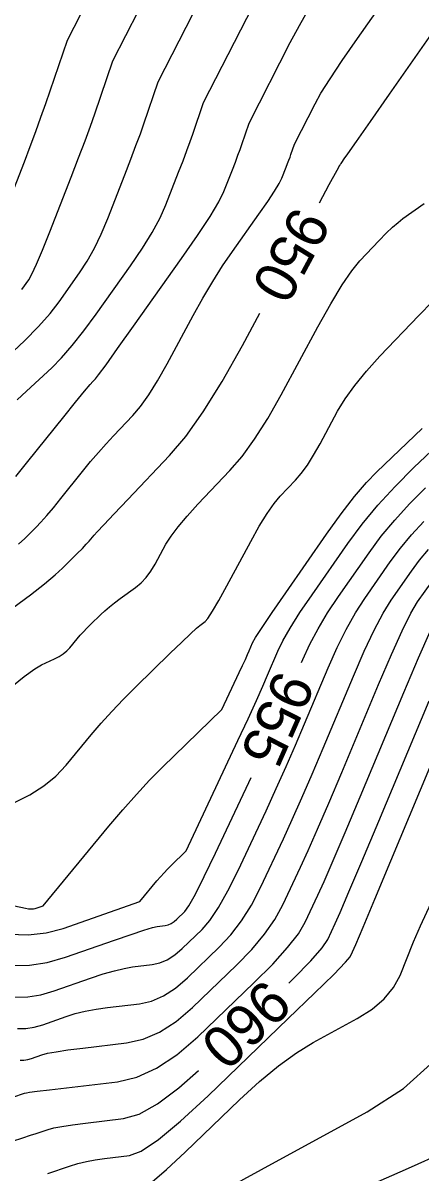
# Model space of a CAD drawing. Extents: x 2175772 to 2185556, y 721391 to 722853.
# Drawn here: x 2178685.3 to 2178711.9, y 721892.9 to 721969.8 of the extents above; entities that cross this region are included whole.
import ezdxf

# ---------------------------------------------------------------- set-up
doc = ezdxf.new("R2010")
doc.units = 0
doc.layers.add('DT_X_Contour_Major', color=7, linetype='Continuous')
doc.layers.add('DT_X_Contour_Minor', color=7, linetype='Continuous')

msp = doc.modelspace()

# ---------------------------------------------------------------- linework, layer by layer
at = {"layer": 'DT_X_Contour_Major'}
for points in [[(2178685.222, 721952.012), (2178685.682, 721952.66), (2178685.9, 721953.044), (2178686.208, 721953.709), (2178686.606, 721954.655), (2178687.095, 721955.883), (2178688.519, 721959.531), (2178689.019, 721960.823), (2178689.449, 721961.962), (2178689.811, 721962.948), (2178690.104, 721963.781), (2178691.309, 721967.314), (2178694.779, 721974.115)], [(2178705.132, 721957.827), (2178705.785, 721959.035), (2178706.309, 721960.006), (2178706.486, 721960.33), (2178706.491, 721960.336), (2178706.493, 721960.338), (2178706.495, 721960.34), (2178706.497, 721960.341), (2178706.498, 721960.342), (2178706.504, 721960.347), (2178706.508, 721960.35), (2178706.516, 721960.361), (2178706.538, 721960.394), (2178706.575, 721960.448), (2178706.626, 721960.523), (2178706.782, 721960.753), (2178707.015, 721961.089), (2178707.6, 721961.925), (2178708.536, 721963.261), (2178709.823, 721965.097), (2178713.722, 721970.66)], [(2178684.621, 721930.711), (2178685.792, 721931.595), (2178686.736, 721932.333), (2178687.451, 721932.925), (2178687.938, 721933.37), (2178688.933, 721934.363), (2178689.269, 721934.701), (2178689.533, 721934.972), (2178689.724, 721935.175), (2178689.842, 721935.31), (2178690.06, 721935.581), (2178690.262, 721935.807), (2178690.704, 721936.283), (2178691.387, 721937.006), (2178692.31, 721937.979), (2178695.092, 721940.905), (2178696.18, 721942.188), (2178697.355, 721943.843), (2178698.618, 721945.87), (2178699.97, 721948.268), (2178701.141, 721950.436)], [(2178703.934, 721927.057), (2178704.022, 721927.265), (2178704.486, 721928.283), (2178705.037, 721929.324), (2178705.674, 721930.389), (2178706.398, 721931.477), (2178708.445, 721934.411), (2178709.257, 721935.507), (2178710.158, 721936.596), (2178711.149, 721937.677), (2178712.23, 721938.75)], [(2178703.08, 721905.601), (2178703.402, 721905.917), (2178704.541, 721907.095), (2178705.3, 721907.964), (2178705.679, 721908.523), (2178706.186, 721909.601), (2178706.51, 721910.332), (2178707.102, 721911.717), (2178707.963, 721913.754), (2178709.092, 721916.445), (2178712.46, 721924.491)], [(2178684.585, 721906.794), (2178685.739, 721906.81), (2178686.925, 721906.993), (2178688.141, 721907.342), (2178691.427, 721908.496), (2178692.529, 721908.877), (2178693.373, 721909.156), (2178693.958, 721909.333), (2178694.284, 721909.408), (2178694.809, 721909.469), (2178695.006, 721909.513), (2178695.203, 721909.599), (2178695.4, 721909.726), (2178695.598, 721909.895), (2178696.123, 721910.4), (2178696.4, 721910.787), (2178696.835, 721911.569), (2178697.428, 721912.746), (2178698.18, 721914.318), (2178700.395, 721919.035), (2178700.551, 721919.369)], [(2178676.882, 721892.488), (2178678.768, 721893.126), (2178680.261, 721893.626), (2178681.363, 721893.989), (2178683.777, 721894.774), (2178684.606, 721895.044), (2178685.283, 721895.265), (2178685.809, 721895.437), (2178686.182, 721895.561), (2178686.975, 721895.826), (2178687.355, 721895.926), (2178687.898, 721896.03), (2178688.604, 721896.137), (2178689.475, 721896.248), (2178692.014, 721896.546), (2178693.06, 721896.849), (2178694.296, 721897.534), (2178695.72, 721898.602), (2178697.027, 721899.777)]]:
    msp.add_lwpolyline(points, dxfattribs=at)
at = {"layer": 'DT_X_Contour_Minor'}
for points in [[(2178684.291, 721947.527), (2178685.401, 721948.586), (2178686.341, 721949.55), (2178687.111, 721950.42), (2178687.712, 721951.195), (2178689.089, 721953.135), (2178689.594, 721953.908), (2178690.077, 721954.773), (2178690.537, 721955.73), (2178690.975, 721956.779), (2178692.114, 721959.697), (2178692.514, 721960.73), (2178692.858, 721961.641), (2178693.148, 721962.43), (2178693.382, 721963.096), (2178694.346, 721965.922), (2178699.503, 721976.031)], [(2178684.993, 721934.981), (2178685.421, 721935.363), (2178686.184, 721936.124), (2178686.502, 721936.458), (2178686.884, 721936.89), (2178687.331, 721937.419), (2178687.841, 721938.046), (2178689.289, 721939.849), (2178689.825, 721940.505), (2178690.348, 721941.119), (2178690.856, 721941.693), (2178691.35, 721942.226), (2178692.649, 721943.592), (2178693.157, 721944.192), (2178693.707, 721944.966), (2178694.298, 721945.915), (2178694.932, 721947.039), (2178696.676, 721950.269), (2178697.331, 721951.445), (2178697.988, 721952.553), (2178698.648, 721953.591), (2178699.31, 721954.56), (2178701.078, 721957.052), (2178701.671, 721957.903), (2178702.125, 721958.59), (2178702.44, 721959.111), (2178702.616, 721959.466), (2178702.9, 721960.193), (2178703, 721960.451), (2178703.085, 721960.678), (2178703.158, 721960.874), (2178703.216, 721961.04), (2178703.456, 721961.744), (2178704.83, 721964.437), (2178705.229, 721965.144), (2178705.837, 721966.11), (2178706.655, 721967.336), (2178707.682, 721968.821), (2178710.7, 721973.126)], [(2178683.492, 721955.696), (2178685.391, 721960.564), (2178685.786, 721961.59), (2178686.157, 721962.582), (2178686.503, 721963.541), (2178686.826, 721964.467), (2178688.273, 721968.706), (2178690.054, 721972.199)], [(2178684.917, 721944.631), (2178685.533, 721945.222), (2178687.218, 721946.783), (2178687.879, 721947.446), (2178688.597, 721948.267), (2178689.371, 721949.244), (2178690.202, 721950.377), (2178692.496, 721953.61), (2178693.288, 721954.773), (2178693.945, 721955.838), (2178694.468, 721956.805), (2178694.856, 721957.674), (2178695.71, 721959.862), (2178696.009, 721960.637), (2178696.267, 721961.32), (2178696.484, 721961.911), (2178696.66, 721962.411), (2178697.383, 721964.529), (2178701.516, 721972.631)], [(2178684.818, 721939.515), (2178685.629, 721940.518), (2178688.024, 721943.5), (2178688.819, 721944.487), (2178689.406, 721945.21), (2178689.787, 721945.67), (2178689.96, 721945.866), (2178690.146, 721946.038), (2178690.357, 721946.307), (2178690.852, 721946.983), (2178691.631, 721948.068), (2178692.693, 721949.56), (2178695.902, 721954.084), (2178696.982, 721955.637), (2178697.814, 721956.902), (2178698.399, 721957.88), (2178698.736, 721958.57), (2178699.305, 721960.028), (2178699.504, 721960.544), (2178699.676, 721960.999), (2178699.821, 721961.393), (2178699.938, 721961.726), (2178700.42, 721963.137), (2178703.173, 721968.534), (2178703.782, 721969.678), (2178704.428, 721970.797)], [(2178684.41, 721925.34), (2178685.376, 721926.118), (2178686.086, 721926.644), (2178686.539, 721926.916), (2178687.408, 721927.306), (2178687.717, 721927.463), (2178687.991, 721927.639), (2178688.23, 721927.835), (2178688.435, 721928.052), (2178688.934, 721928.656), (2178689.13, 721928.885), (2178689.344, 721929.121), (2178689.574, 721929.362), (2178689.822, 721929.609), (2178690.506, 721930.276), (2178690.779, 721930.53), (2178691.084, 721930.791), (2178691.422, 721931.06), (2178691.793, 721931.335), (2178692.825, 721932.081), (2178693.197, 721932.388), (2178693.54, 721932.75), (2178693.855, 721933.168), (2178694.14, 721933.641), (2178694.863, 721934.976), (2178695.2, 721935.519), (2178695.669, 721936.148), (2178696.27, 721936.861), (2178697.003, 721937.659), (2178699.135, 721939.901), (2178699.95, 721940.849), (2178700.794, 721942.012), (2178701.667, 721943.39), (2178702.57, 721944.982), (2178705.018, 721949.514), (2178705.882, 721951.066), (2178706.638, 721952.32), (2178707.287, 721953.278), (2178707.829, 721953.938), (2178709.129, 721955.305), (2178709.594, 721955.78), (2178710.013, 721956.181), (2178710.386, 721956.508), (2178710.712, 721956.761), (2178712.129, 721957.767)], [(2178684.726, 721917.688), (2178685.764, 721918.213), (2178686.686, 721918.807), (2178687.491, 721919.467), (2178688.179, 721920.196), (2178689.86, 721922.228), (2178690.519, 721923), (2178691.236, 721923.792), (2178692.012, 721924.604), (2178692.846, 721925.435), (2178695.146, 721927.678), (2178695.917, 721928.426), (2178696.505, 721928.987), (2178696.909, 721929.361), (2178697.13, 721929.548), (2178697.474, 721929.796), (2178697.662, 721930.017), (2178697.968, 721930.491), (2178698.392, 721931.219), (2178698.933, 721932.201), (2178700.533, 721935.159), (2178701.106, 721936.18), (2178701.625, 721937.024), (2178702.089, 721937.692), (2178702.5, 721938.184), (2178703.523, 721939.259), (2178703.913, 721939.714), (2178704.318, 721940.272), (2178704.737, 721940.933), (2178705.17, 721941.696), (2178706.345, 721943.871), (2178706.852, 721944.712), (2178707.492, 721945.605), (2178708.265, 721946.55), (2178709.172, 721947.547), (2178711.768, 721950.274), (2178712.695, 721951.222)], [(2178684.35, 721908.885), (2178685.637, 721908.845), (2178686.849, 721908.976), (2178687.987, 721909.277), (2178693.123, 721911.081), (2178694.257, 721912.451), (2178694.497, 721912.735), (2178694.731, 721912.999), (2178694.959, 721913.243), (2178695.181, 721913.466), (2178696.204, 721914.464), (2178699.67, 721921.843), (2178700.352, 721923.302), (2178700.911, 721924.517), (2178701.347, 721925.486), (2178701.661, 721926.212), (2178702.334, 721927.82), (2178702.667, 721928.509), (2178703.161, 721929.368), (2178703.816, 721930.398), (2178704.633, 721931.599), (2178707.025, 721935.028), (2178707.974, 721936.31), (2178709.028, 721937.583), (2178710.187, 721938.846), (2178711.45, 721940.1), (2178714.958, 721943.433)], [(2178679.306, 721911.928), (2178685.457, 721910.623), (2178685.663, 721910.588), (2178685.842, 721910.574), (2178685.994, 721910.581), (2178686.12, 721910.61), (2178686.645, 721910.795), (2178691.046, 721916.115), (2178691.977, 721917.217), (2178692.886, 721918.241), (2178693.771, 721919.187), (2178694.634, 721920.056), (2178698.606, 721923.929), (2178699.759, 721926.385), (2178699.986, 721926.871), (2178700.172, 721927.275), (2178700.318, 721927.598), (2178700.422, 721927.84), (2178700.646, 721928.375), (2178700.848, 721928.735), (2178701.286, 721929.412), (2178701.959, 721930.408), (2178702.868, 721931.721), (2178705.605, 721935.646), (2178706.585, 721937.011), (2178707.471, 721938.163), (2178708.263, 721939.102), (2178708.961, 721939.828), (2178712.001, 721942.716)], [(2178684.763, 721904.684), (2178685.614, 721904.695), (2178686.488, 721904.83), (2178687.385, 721905.087), (2178689.807, 721905.938), (2178690.664, 721906.225), (2178691.419, 721906.446), (2178692.071, 721906.602), (2178692.621, 721906.693), (2178693.949, 721906.849), (2178694.448, 721906.96), (2178694.947, 721907.177), (2178695.445, 721907.499), (2178695.945, 721907.926), (2178697.276, 721909.206), (2178697.8, 721909.813), (2178698.376, 721910.674), (2178699.002, 721911.79), (2178699.68, 721913.159), (2178701.554, 721917.148), (2178702.242, 721918.633), (2178702.902, 721920.096), (2178703.534, 721921.537), (2178704.138, 721922.956), (2178705.709, 721926.711), (2178706.305, 721928.057), (2178706.912, 721929.28), (2178707.532, 721930.379), (2178708.164, 721931.355), (2178709.864, 721933.794), (2178710.539, 721934.705), (2178711.289, 721935.61), (2178712.112, 721936.508)], [(2178684.941, 721902.573), (2178685.489, 721902.58), (2178686.051, 721902.667), (2178686.629, 721902.833), (2178688.188, 721903.38), (2178688.799, 721903.572), (2178689.465, 721903.735), (2178690.184, 721903.871), (2178690.957, 721903.979), (2178693.089, 721904.229), (2178693.889, 721904.408), (2178694.69, 721904.755), (2178695.49, 721905.272), (2178696.292, 721905.958), (2178698.428, 721908.012), (2178699.201, 721908.839), (2178699.917, 721909.78), (2178700.577, 721910.833), (2178701.179, 721912), (2178702.712, 721915.261), (2178703.309, 721916.558), (2178703.952, 721918.001), (2178704.641, 721919.591), (2178705.376, 721921.328), (2178707.397, 721926.156), (2178708.124, 721927.831), (2178708.788, 721929.235), (2178709.39, 721930.37), (2178709.929, 721931.233), (2178711.284, 721933.176), (2178711.822, 721933.902), (2178712.419, 721934.623)], [(2178685.119, 721900.462), (2178685.364, 721900.466), (2178685.615, 721900.504), (2178685.873, 721900.578), (2178686.568, 721900.823), (2178686.934, 721900.919), (2178687.51, 721901.025), (2178688.296, 721901.14), (2178689.293, 721901.264), (2178692.23, 721901.609), (2178693.331, 721901.855), (2178694.433, 721902.333), (2178695.536, 721903.045), (2178696.638, 721903.989), (2178699.58, 721906.818), (2178700.601, 721907.865), (2178701.458, 721908.885), (2178702.151, 721909.877), (2178702.679, 721910.841), (2178703.87, 721913.375), (2178704.376, 721914.483), (2178705.002, 721915.906), (2178705.749, 721917.646), (2178706.615, 721919.701), (2178709.085, 721925.601), (2178709.943, 721927.605), (2178710.663, 721929.191), (2178711.247, 721930.36), (2178711.694, 721931.112), (2178712.704, 721932.559)], [(2178684.629, 721897.986), (2178685.412, 721898.241), (2178685.541, 721898.284), (2178685.744, 721898.317), (2178686.254, 721898.383), (2178687.073, 721898.483), (2178688.199, 721898.617), (2178691.614, 721899.018), (2178692.91, 721899.318), (2178694.237, 721899.919), (2178695.596, 721900.82), (2178696.985, 721902.021), (2178700.733, 721905.624), (2178702.002, 721906.891), (2178702.999, 721907.99), (2178703.725, 721908.92), (2178704.179, 721909.682), (2178705.028, 721911.488), (2178705.443, 721912.408), (2178706.052, 721913.811), (2178706.856, 721915.7), (2178707.853, 721918.073), (2178710.772, 721925.046), (2178711.761, 721927.379), (2178712.539, 721929.147)], [(2178686.952, 721892.881), (2178688.41, 721893.367), (2178688.966, 721893.536), (2178689.542, 721893.677), (2178690.136, 721893.791), (2178690.75, 721893.878), (2178692.414, 721894.074), (2178693.211, 721894.379), (2178694.354, 721895.149), (2178695.843, 721896.384), (2178697.679, 721898.084), (2178703.037, 721903.236), (2178704.803, 721904.943), (2178706.082, 721906.2), (2178706.874, 721907.007), (2178707.179, 721907.364), (2178707.344, 721907.714), (2178707.55, 721908.193), (2178708.045, 721909.364), (2178708.828, 721911.23), (2178709.9, 721913.788), (2178713.143, 721921.536)], [(2178693.94, 721892.311), (2178694.905, 721893.145), (2178696.138, 721894.3), (2178699.784, 721897.806), (2178701.117, 721899.031), (2178702.384, 721900.078), (2178703.583, 721900.947), (2178704.716, 721901.638), (2178707.647, 721903.243), (2178708.651, 721903.874), (2178709.464, 721904.565), (2178710.086, 721905.315), (2178710.517, 721906.125), (2178711.413, 721908.365), (2178711.875, 721909.442), (2178712.59, 721910.995)], [(2178698.897, 721891.85), (2178701.255, 721893.136), (2178708.308, 721896.996), (2178710.745, 721898.571), (2178712.768, 721900.398)], [(2178703.879, 721890.064), (2178711.091, 721893.244), (2178713.476, 721894.295)]]:
    msp.add_lwpolyline(points, dxfattribs=at)

# ---------------------------------------------------------------- texts
at = {"layer": 'DT_X_Contour_Major'}
for s, rotation, p in [('950', 241.62861, (2178703.486, 721957.726)), ('955', 246.24721, (2178702.307, 721926.689)), ('960', 223.89327, (2178701.507, 721906.011))]:
    msp.add_text(s, height=2.8, rotation=rotation, dxfattribs=at).set_placement(p)

doc.saveas('drawing.dxf')
